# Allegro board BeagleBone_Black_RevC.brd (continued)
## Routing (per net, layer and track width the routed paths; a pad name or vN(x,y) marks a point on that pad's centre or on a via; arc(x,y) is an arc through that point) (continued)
PMIC_POWR_EN: length 66.7
  TOP w0.121: v1(18.29,14.24) U2.9 ; v1(48.92,23.61) U5.C6
  LYR3 w0.133: v1(18.29,14.24) 18.34,14.24 19.56,13.02 19.56,9.65 20.19,9.02 27.3,9.02 29.44,6.88 39.09,6.88 39.37,6.6 55.88,6.6 57.02,7.75 v1(57.02,10.92)
  LYR4 w0.133: v1(57.02,10.92) 56.39,10.92 54.48,12.83 54.48,14.86 52.58,16.76 51.31,16.76 50.67,17.4 50.67,20.7 48.92,22.45 v1(48.92,23.61)
PROC_A15: length 15.2
  TOP w0.121: v1(39.88,11.94) 38.86,12.95 38.86,15.88 38.34,16.4 38.34,20.18 39.62,21.46 40.37,21.46 40.92,22.01 U5.A15
  BOTTOM w0.121: v1(39.88,11.94) 40.39,12.45 41.4,12.45 R18.1
PWR_BUT: length 58
  TOP w0.121: v1(14.35,40.39) 11.56,40.39 10.83,41.11 S3.2 S3.4 ; U2.25 25.93,12.55 26.42,12.06 v1(26.92,12.06)
  LYR4 w0.133: v1(14.35,40.39) 14.35,40 15.89,38.46 15.89,24.03 17.44,22.48 19.05,22.48 21.21,20.32 24.13,20.32 25.65,18.8 25.65,13.34 v1(26.92,12.06) 28.57,10.41 28.57,3.17 P9.9
PWR_LEDR: length 2.3
  TOP w0.121: v1(3.05,17.27) 2.98,17.21 D1.1
  BOTTOM w0.121: R12.2 3.3,17.02 v1(3.05,17.27)
RBIAS: length 2.7
  TOP w0.121: v1(21.27,28.26) 21.91,28.89 21.91,29.21 22.06,29.36 U14.32
  BOTTOM w0.121: v1(21.27,28.26) R144.1
RCLKIN: length 7.8
  TOP w0.121: U14.5 25.33,27.94 25.34,27.94 v1(25.34,27.69)
  BOTTOM w0.121: 26.04,26.29 25.78,26.54 25.78,27.24 v1(25.34,27.69) ; 26.04,26.29 26.1,26.29 26.73,26.92 28.57,26.92 28.83,26.67 28.83,26.04 29.08,25.78 29.72,25.78 R140.2 ; 26.04,26.29 R142.2
REFCLKO: length 6.2
  TOP w0.121: U14.7 26.33,28.21 26.92,27.62 28.13,27.62 28.77,26.99 v1(29.21,26.99) R124.2 R118.1
  BOTTOM w0.121: R124.2 v1(29.21,26.99)
RXD0/MODE0: length 4.1
  TOP w0.121: U14.11 28.59,30.36 29.02,30.8 v1(29.21,30.8) 29.21,30.48 29.34,30.35 29.84,30.35 29.97,30.48 R128.2
  BOTTOM w0.121: R128.2 v1(29.21,30.8)
RXD1/MODE1: length 4
  TOP w0.121: R127.2 29.97,29.46 29.88,29.37 29.34,29.37 29.21,29.5 v1(29.21,29.84) 29.19,29.86 28.89,29.86 U14.10
  BOTTOM w0.121: R127.2 v1(29.21,29.84)
RXD2/RMIISEL: length 4.1
  TOP w0.121: U14.9 28.74,29.36 v1(29.21,28.89) 29.21,28.57 29.34,28.45 29.84,28.45 29.97,28.57 R126.2
  BOTTOM w0.121: R126.2 v1(29.21,28.89)
RXD3/PHYAD2: length 4.3
  TOP w0.121: R125.2 v1(29.21,27.94) 28.81,28.34 26.96,28.34 26.83,28.47 U14.8
  BOTTOM w0.121: R125.2 v1(29.21,27.94)
RXDV: length 2.8
  TOP w0.121: U14.26 22.28,32.37 21.72,32.92 21.72,33.27 21.34,33.66 v1(21.16,33.66)
  BOTTOM w0.121: R129.2 v1(21.16,33.66)
RXER/PHYAD0: length 4.1
  TOP w0.121: U14.13 28.83,31.37 v1(29.21,31.75) 29.21,31.4 29.34,31.27 29.88,31.27 29.97,31.37 R133.2
  BOTTOM w0.121: R133.2 v1(29.21,31.75)
RXN: length 18.4
  TOP w0.095: P5.2 17.14,33.92 16.89,34.17 16.26,34.17 16,33.92 16,32.64 16.64,32 17.64,32 18.43,32.79 19.29,32.79 20.09,31.99 20.09,30.39 20.66,29.83 20.94,29.83 v1(21.27,30.16) 21.34,30.23 21.9,30.23 22.03,30.36 U14.30
  BOTTOM w0.095: R121.1 v1(21.27,30.16)
  BOTTOM w0.121: C138.1 P5.2
RXP: length 15.9
  TOP w0.095: U14.31 22.02,29.86 21.93,29.95 21.68,29.95 21.53,29.79 21.53,29.46 v1(21.27,29.21) 20.94,29.55 20.54,29.55 19.81,30.28 19.81,31.88 19.18,32.51 18.54,32.51 17.75,31.72 16.52,31.72 15.72,32.52 15.72,34.04 15.47,34.29 P5.1
  BOTTOM w0.095: R120.1 v1(21.27,29.21)
  BOTTOM w0.121: C137.1 P5.1
SD_CLK: length 73.1
  TOP w0.121: R152.2 71.63,35.81 v1(72.01,35.43) ; v1(31.75,20.32) 31.75,20.7 29.97,22.48 R16.2 C5.1
  LYR3 w0.133: v1(72.01,35.43) 71.63,35.81 68.58,35.81 67.69,34.92 67.69,33.27 69.22,31.75 69.22,17.84 66.22,14.85 53.85,14.85 52.96,15.75 48.13,15.75 46.35,17.53 40.89,17.53 40.64,17.78 39.62,17.78 38.86,17.02 33.78,17.02 31.74,19.06 31.74,20.31 v1(31.75,20.32)
  BOTTOM w0.121: v1(72.01,35.43) 71.78,35.66 P10.5
SD_CMD: length 11
  TOP w0.121: R151.2 72.01,42.67 72.13,42.55 72.14,42.55 v1(72.52,42.16)
  BOTTOM w0.121: R15.2 69.09,38.35 69.58,37.86 P10.3 72.28,37.86 73.03,38.61 73.03,41.66 v1(72.52,42.16)
SD_DAT0: length 10.4
  BOTTOM w0.121: R153.2 72.77,28.26 73.53,29.02 73.53,31.22 71.29,33.46 P10.7 70.11,33.46 69.28,34.29 68.07,34.29 R31.2
SD_DAT1: length 11.4
  BOTTOM w0.121: R32.2 68.07,33.91 68.96,33.91 69.3,33.57 69.3,33.13 69.52,32.92 69.52,32.5 69.66,32.36 P10.8 71.91,32.36 73.15,31.11 73.15,29.22 72.91,28.96 71.76,28.96 71.5,28.7 R154.2
SD_DAT2: length 7.1
  TOP w0.121: R150.2 70.1,42.93 70.6,42.43 70.6,42.43 v1(70.87,42.16)
  BOTTOM w0.121: R2.2 68.33,41.27 69.54,40.06 P10.1 70.7,40.06 70.87,40.23 v1(70.87,42.16)
SD_DAT3: length 10.4
  TOP w0.121: R155.2 71.06,42.86 v1(71.75,42.16)
  BOTTOM w0.121: R13.2 68.96,39.24 69.24,38.96 P10.2 71.29,38.96 71.64,38.61 72.39,38.61 72.64,38.86 72.64,41.27 v1(71.75,42.16)
SPI1_CS0: length 76.1
  TOP w0.121: U11.25 63.75,35.31 v1(64.26,34.8) ; v1(43.32,23.61) U5.C12
  LYR4 w0.133: v1(43.32,23.61) 43.32,22.72 44.32,21.72 44.32,19.94 44.07,19.68 44.07,15.49 44.58,14.99 46.48,14.99 51.56,9.91 51.56,5.59 P9.28 ; v1(64.26,34.8) 64.77,34.29 69.85,34.29 71.12,33.02 71.12,18.41 70.36,17.65 69.28,17.65 66.1,14.48 61.59,14.48 58.92,11.8 57.66,11.8 v1(57.02,12.45)
  BOTTOM w0.121: v1(57.02,12.45) 57.53,11.94 57.53,8.25 54.61,5.33 53.59,5.33 P9.28
SPI1_D0: length 81.5
  TOP w0.121: v1(63.63,34.8) 63.25,35.17 U11.24 ; U5.B13 v1(42.52,22.81)
  LYR4 w0.133: v1(57.78,12.45) 58.19,12.04 58.78,12.04 61.47,14.73 65.85,14.73 69.15,18.03 70.23,18.03 70.87,18.67 70.87,32.89 69.72,34.04 64.39,34.04 v1(63.63,34.8) ; v1(42.52,22.81) 42.11,22.4 42.11,21.64 43.56,20.19 43.56,14.99 44.04,14.5 46.02,14.5 49.02,11.5 49.02,4.06 49.78,3.3 51.82,3.3 52.07,3.05 54.1,3.05 55.24,1.91
  BOTTOM w0.121: 55.24,1.91 56.26,2.92 56.26,6.48 57.78,8 v1(57.78,12.45)
SPI1_D1: length 26.9
  TOP w0.121: v1(43.32,24.41) U5.D12
  LYR4 w0.121: 43.72,23.11 43.72,24.01 v1(43.32,24.41)
  LYR4 w0.133: 43.72,23.11 44.7,22.13 44.7,19.81 44.32,19.42 44.32,15.75 44.83,15.24 46.74,15.24 53.98,8 53.98,7.24 55.24,5.97 55.24,4.45
SPI1_SCLK: length 81.1
  TOP w0.121: U5.A13 v1(42.52,22.01) ; U11.23 62.75,35.04 v1(62.99,34.8)
  LYR4 w0.133: v1(62.99,34.8) 64.01,33.78 69.6,33.78 70.61,32.77 70.61,18.92 70.1,18.41 69.02,18.41 65.6,14.99 61.09,14.99 v1(58.55,12.45) ; v1(42.52,22.01) 43.27,22.01 44.07,21.21 44.07,20.19 43.81,19.94 43.81,15.24 44.32,14.74 46.22,14.74 51.31,9.65 51.31,4.32 52.32,3.3 56.39,3.3 P9.31
  BOTTOM w0.121: P9.31 56.52,3.17 56.52,6.22 58.04,7.75 58.04,11.94 v1(58.55,12.45)
SYS_5V: length 117.7
  TOP w0.203: U2.2 19.15,17.04 v1(18.8,17.4) ; U2.42 23.06,19 v1(22.99,19.11) ; U2.21 23.86,11.45 v1(24.13,11.18) 24.26,11.31 U2.22 ; U2.39 v1(24.26,19.11) ; v1(26.92,16.45) 26.92,16.19 26.57,15.84 U2.32 ; U2.7 19.04,15.04 v1(18.8,14.8) 18.95,14.64 U2.8
  TOP w0.381: v1(7.62,45.33) 7.54,45.4 R74.1 ; R71.1 v1(7.62,44.45) ; R72.1 v1(7.62,47.31) ; R73.1 7.59,46.35 v1(7.62,46.39)
  TOP w0.762: RT1.1 67.88,8.19 C34.1
  LYR3 w0.381: 19.09,14.87 18.87,14.87 v1(18.8,14.8) 18.28,14.8 v1(18.24,14.84)
  LYR3 w0.508: 19.62,17.4 19.62,15.41 19.09,14.87 ; v1(8.81,15.24) 8.84,15.27 8.95,15.27 9.53,15.84 v1(9.53,15.86) 10.55,16.89 17.96,16.89 18.36,17.3 18.69,17.3 v1(18.8,17.4)
  LYR3 w0.762: 24.26,17.4 v1(24.26,19.11) ; 24.26,17.4 v1(18.8,17.4) ; 24.26,17.4 25.97,17.4 v1(26.92,16.45) 26.92,15.56 24.13,12.76 v1(24.13,11.18)
  LYR4 w0.381: v1(7.62,47.31) v1(7.62,46.39) v1(7.62,45.33) v1(7.62,44.45) 12.95,39.12 12.95,36.45 12.45,35.94 12.45,23.62 12.95,23.11 12.95,19.3 9.9,16.25 9.9,16.23 v1(9.53,15.86) ; 19.06,14.94 18.94,14.94 v1(18.8,14.8) 18.28,14.8 v1(18.24,14.84)
  LYR4 w0.508: 19.06,14.94 19.43,15.3 19.43,16.76 v1(18.8,17.4)
  LYR4 w0.762: P9.8 27.3,5.97 23.75,9.53 23.75,10.79 v1(24.13,11.18)
  LYR5_PWR w0.889: 28.04,3.71 P9.8 26.57,3.71 ; 67.17,9.03 RT1.1 ; RT1.1 67.17,7.48 ; RT1.1 68.72,7.48 ; RT1.1 68.72,9.03 ; 26.57,2.64 P9.7 28.04,2.64
  BOTTOM w0.381: U8.2 75.86,14.28 v1(75.54,14.61) 75.86,14.93 U8.3 ; v1(24.26,19.11) 24.26,18.48 C13.2 23.5,18.35 23.5,18.86 23.24,19.11 v1(22.99,19.11) ; C10.2 19.11,14.22 18.8,14.54 v1(18.8,14.8) ; v1(24.13,11.18) 23.81,11.49 C7.2 C8.2
  BOTTOM w0.508: 8.76,15.24 v1(8.81,15.24)
  BOTTOM w0.635: U4.2 9.54,15.88 v1(9.53,15.86)
  BOTTOM w0.762: P9.7 P9.8
SYS_RESETN: length 97.2
  TOP w0.121: v1(42.42,16.51) 41.91,16.51 41.66,16.76 41.66,18.8 42.8,19.94 43.81,19.94 44.7,20.83 44.7,21.46 45.32,22.08 U5.A10 ; S1.4 S1.2 v1(9.99,49.4) ; U16.4 31.1,5.7 P9.10
  LYR3 w0.133: v1(34.29,16.19) 34.73,15.75 38.1,15.75 38.35,16 41.91,16 v1(42.42,16.51)
  LYR4 w0.133: P9.10 28.96,5.33 28.96,10.73 v1(27.62,12.06) 27.62,12.89 30.48,15.75 30.48,18.29 v1(29.97,18.8) 28.83,19.94 28.83,22.99 29.72,23.88 29.72,36.34 v1(28.95,37.11) 27.77,38.28 22.16,38.28 11.04,49.4 v1(9.99,49.4)
  BOTTOM w0.121: v1(27.62,12.06) R14.2 C24.1 C30.1 ; v1(29.97,18.8) 30.48,18.29 30.48,16.51 30.8,16.19 P2.15 v1(34.29,16.19) ; U1.2 29.29,38.1 28.95,37.76 v1(28.95,37.11)
TCT_RCT: length 6.4
  BOTTOM w0.121: P5.4 15.88,29.21 P5.5 R137.1 C141.1
TESTOUT: length 2.9
  TOP w0.121: TP3.1 51.44,21.89 U5.A3
TIMER4: length 32.4
  TOP w0.121: v1(48.12,34.01) U5.R7
  LYR3 w0.121: 47.72,35.05 47.72,34.41 v1(48.12,34.01)
  LYR3 w0.133: v1(36.07,47.75) 36.34,47.48 40.02,47.48 41.4,46.1 41.4,44.45 46.75,39.1 46.75,36.31 47.72,35.34 47.72,35.05
  LYR4 w0.133: P8.7 27.3,49.02 28.57,47.75 33.4,47.75 34.04,48.39 35.43,48.39 v1(36.07,47.75)
TIMER5: length 28.8
  TOP w0.121: v1(48.92,34.81) U5.T6
  LYR3 w0.133: v1(48.92,34.81) 48.92,35.15 48.39,35.69 48.39,38.61 42.14,44.86 42.14,46.38 40.13,48.39 v1(36.83,48.39)
  LYR4 w0.133: P8.9 30.86,49.15 36.07,49.15 v1(36.83,48.39)
TIMER6: length 35.7
  TOP w0.121: U5.U6 48.92,35.61 48.92,37.24 49.4,37.72 49.4,38.35 49.02,38.73 49.02,43.84 v1(49.25,44.07)
  BOTTOM w0.121: v1(49.25,44.07) 49.25,44.04 49.15,43.94 47.5,43.94 46.99,44.45 40.01,44.45 38.86,45.59 38.86,50.93 38.23,51.56 30.99,51.56 P8.10
TIMER7: length 32.7
  TOP w0.121: v1(48.12,34.81) U5.T7
  LYR3 w0.133: v1(36.07,48.39) 36.58,47.88 40.13,47.88 41.78,46.23 41.78,44.58 48.12,38.24 v1(48.12,34.81)
  LYR4 w0.133: P8.8 28.57,51.44 28.57,49.78 29.59,48.77 35.69,48.77 v1(36.07,48.39)
TXCLK: length 6
  TOP w0.121: v1(29.21,35.56) 28.83,35.18 27.94,35.18 27.67,35.45 26.55,35.45 25.33,34.24 U14.20
  BOTTOM w0.121: R134.2 v1(29.21,35.56)
TXD0: length 4.2
  TOP w0.121: R39.2 21.84,35.94 23.11,34.67 23.65,34.67 24.33,33.99 U14.22
TXD1: length 3.3
  TOP w0.121: R40.2 22.1,35.05 22.73,34.42 23.33,34.42 23.83,33.92 U14.23
TXD2: length 7.8
  TOP w0.121: U14.24 23.33,33.92 23.11,34.14 22.5,34.14 22.07,34.58 19.4,34.58 19.18,34.8 19.18,36.45 19.56,36.83 R41.2
TXD3: length 8.6
  TOP w0.121: R42.2 19.82,37.72 18.8,36.7 18.8,34.67 19.3,34.16 21.21,34.16 21.32,34.05 21.32,34.05 21.56,33.82 21.56,33.81 22.05,33.32 22.05,33.09 22.28,32.87 U14.25
TXEN: length 1.7
  TOP w0.121: R38.2 25.02,34.92 25.02,34.42 24.83,34.24 U14.21
TXN: length 20.3
  TOP w0.095: v1(21.27,32.07) 21.27,31.69 21.59,31.37 U14.28
  LYR3 w0.102: v1(21.27,32.07) 20.88,31.68 20.88,31.16 19.81,30.09 19.81,28.45 18.21,26.85 16.71,26.85 15.9,27.66 15.9,29.09 16.15,29.34 16.89,29.34 17.14,29.09 P5.6
  BOTTOM w0.095: R123.1 v1(21.27,32.07)
  BOTTOM w0.121: P5.6 C140.1
TXP: length 17.8
  TOP w0.095: v1(21.27,31.11) 21.27,31.1 21.28,31.09 21.81,31.09 22.03,30.86 U14.29
  LYR3 w0.102: P5.3 15.6,30.76 15.6,27.53 16.59,26.54 18.34,26.54 20.12,28.32 20.12,29.96 v1(21.27,31.11)
  BOTTOM w0.095: R122.1 v1(21.27,31.11)
  BOTTOM w0.121: C139.1 P5.3
U5_H18: length 4.2
  TOP w0.121: U5.H18 38.1,28.01 37.9,27.81 R28.1
U5_R13: length 10.5
  TOP w0.121: v1(42.52,34.01) U5.R13
  LYR3 w0.121: v1(42.52,34.01) 42.92,34.41 42.92,35.06 42.55,35.43
  LYR3 w0.133: 42.55,35.43 41.91,36.07 41.02,36.07 38.42,38.67 v1(38.42,40.64)
  BOTTOM w0.121: v1(38.42,40.64) R160.1
U5_T13: length 9.9
  TOP w0.121: v1(42.52,34.81) U5.T13
  LYR3 w0.133: v1(37.15,40.64) 37.15,39.31 40.89,35.56 41.78,35.56 42.26,35.09 42.26,35.07 v1(42.52,34.81)
  BOTTOM w0.121: v1(37.15,40.64) R161.1
UART0_RX: length 35.3
  TOP w0.121: v1(40.92,25.21) U5.E15
  LYR4 w0.121: 39.75,25.53 39.83,25.61 40.52,25.61 v1(40.92,25.21)
  LYR4 w0.133: 39.75,25.53 39.19,24.97 39.19,20.24 40.41,19.02 40.41,10.69 v1(39.88,10.16)
  BOTTOM w0.121: U15.6 53.22,11.68 52.32,12.57 50.16,12.57 49.53,11.94 49.53,10.41 48.51,9.4 44.45,9.4 44.2,9.65 40.39,9.65 39.88,10.16 v1(39.88,10.16)
UART0_TX: length 32.2
  TOP w0.121: v1(40.12,25.21) U5.E16
  LYR4 w0.133: v1(40.12,25.21) 39.45,24.54 39.45,21.38 40.65,20.19 40.65,10.66 v1(41.15,10.16)
  BOTTOM w0.121: U15.5 53.23,12.18 52.58,12.83 49.91,12.83 49.28,12.19 49.28,10.67 48.26,9.65 44.7,9.65 44.45,9.91 41.4,9.91 v1(41.15,10.16)
UART1_RXD: length 25.6
  TOP w0.121: v1(40.12,24.41) U5.D16
  LYR4 w0.121: 40.52,21.72 40.52,24.01 v1(40.12,24.41)
  LYR4 w0.133: v1(45.09,8.89) 44.45,9.53 44.45,10.79 41.66,13.59 41.66,20.45 40.52,21.58 40.52,21.72
  BOTTOM w0.121: P9.26 48.77,5.84 47.75,5.84 46.35,7.24 46.35,8.13 45.59,8.89 v1(45.09,8.89)
UART1_TXD: length 23.5
  TOP w0.121: v1(40.92,24.41) U5.D15
  LYR4 w0.121: v1(40.92,24.41) 41.32,24.01 41.32,23.37
  LYR4 w0.133: 41.32,23.37 41.33,23.35 41.33,21.28 41.91,20.7 41.91,13.84 44.07,11.68 44.45,11.68 46.35,9.78 46.35,5.71 P9.24
UART2_RXD: length 22.7
  TOP w0.121: P9.22 43.56,5.97 41.66,5.97 38.61,9.02 38.61,15.75 38.09,16.26 38.09,20.31 39.72,21.94 39.72,22.17 39.72,22.18 U5.A17
UART2_TXD: length 26
  TOP w0.121: P9.21 43.81,3.17 43.81,4.83 43.05,5.59 41.53,5.59 38.35,8.76 38.35,15.62 37.85,16.13 37.85,20.45 39.32,21.92 39.32,22.81 U5.B17
UART4_RXD: length 40.9
  TOP w0.121: v1(36.07,36) 36.64,35.43 36.96,35.43 37.58,34.81 39.32,34.81 U5.T17
  LYR4 w0.133: v1(36.07,36) 35.94,36.13 35.37,36.13 34.54,35.31 34.54,22.99 34.29,22.73 34.29,17.53 33.15,16.38 v1(33.15,6.48)
  BOTTOM w0.121: P9.11 33.66,3.17 33.66,5.4 33.15,5.91 v1(33.15,6.48)
UART4_TXD: length 44.5
  TOP w0.121: U5.U17 39.48,35.21 39.08,35.61 37.67,35.61 37.34,35.94 37.34,37.08 v1(36.83,37.59) ; P9.13 33.66,3.17 33.66,5.08 v1(32.26,6.48)
  LYR4 w0.133: v1(36.83,37.59) 36.42,38 35.71,38 34.04,36.32 34.04,23.24 33.78,22.99 33.78,18.03 32.26,16.51 v1(32.26,6.48)
USB0_DM: length 40.1
  TOP w0.114: U5.N18 38.8,32.13 36.82,32.13 36.07,32.88 36.07,34.26 35.69,34.65 35.2,34.65 33.43,36.42 28.46,36.42 28.08,36.8 23.89,36.8 17.89,42.8 13.13,42.8 13.02,42.69 13.02,42.01 12.92,41.91 U10.2 v1(11.94,41.91)
  BOTTOM w0.114: P4.2 7.04,43.33 7.24,43.54 7.9,43.54 8.79,42.65 11.44,42.65 11.54,42.55 11.54,41.88 11.64,41.78 11.84,41.78 11.94,41.88 v1(11.94,41.91)
USB0_DP: length 40.2
  TOP w0.114: U5.N17 39.32,32.41 36.94,32.41 36.35,32.99 36.35,34.41 35.83,34.92 35.32,34.92 33.54,36.7 28.57,36.7 28.19,37.08 24,37.08 18.01,43.08 12.98,43.08 12.57,42.67 12.57,42.42 U10.1 12.07,42.41 v1(11.94,42.55)
  BOTTOM w0.114: P4.3 6.92,44.13 7.24,43.81 8.02,43.81 8.9,42.93 11.56,42.93 11.82,42.66 11.82,42.66 v1(11.94,42.55)
USB0_ID: length 47.5
  TOP w0.121: v1(15.11,41.4) 14.61,40.89 12.71,40.89 12.58,41.02 U10.3 ; U5.P16 v1(40.12,33.21)
  BOTTOM w0.121: v1(40.12,33.21) 40.52,33.61 40.52,35.05 40.45,35.12 40.45,39.18 40.15,39.48 32.89,39.48 32.56,39.81 28.63,39.81 28.43,40.01 24.38,40.01 23.86,39.48 17.04,39.48 v1(15.11,41.4) 15.11,42.16 13.21,44.07 8.76,44.07 7.98,44.85 7.11,44.85 7.03,44.93 P4.4
USB1_DM: length 69.3
  TOP w0.114: U5.R18 38.8,33.73 38.43,33.73 38.1,33.4 v1(38.1,33.15)
  LYR3 w0.127: v1(78.08,17.14) 77.9,17.32 76.68,17.32 76.06,16.7 74.21,16.7 P3.2 70.11,15.83 68.07,13.79 47.5,13.79 46.61,14.68 40.77,14.68 39.29,13.21 v1(36.07,13.21)
  LYR4 w0.127: v1(38.1,33.15) 37.72,32.77 37.72,22.81 37.26,22.35 37.26,20.65 37.72,20.19 37.72,15.06 36.47,13.81 36.47,13.61 v1(36.07,13.21)
  BOTTOM w0.114: U9.2 78.55,18.41 78.33,18.19 77.93,18.19 77.68,17.94 77.68,17.54 v1(78.08,17.14)
USB1_DP: length 69.3
  TOP w0.114: U5.R17 39.32,34.01 38.32,34.01 v1(37.47,33.15)
  LYR3 w0.127: v1(78.08,17.78) 77.92,17.63 76.56,17.63 75.93,17.01 74.17,17.01 P3.3 73.34,17.72 71.77,16.14 69.99,16.14 67.94,14.1 47.62,14.1 46.74,14.99 40.64,14.99 39.17,13.51 36.4,13.51 v1(36.07,13.84)
  LYR4 w0.127: v1(36.07,13.84) 37.41,15.19 37.41,20.07 36.96,20.52 36.96,22.48 37.41,22.94 37.41,33.1 v1(37.47,33.15)
  BOTTOM w0.114: v1(78.08,17.78) 78.21,17.92 U9.1
USB1_DRVVBUS: length 52.5
  TOP w0.121: U5.F15 v1(40.92,26.01)
  LYR3 w0.133: v1(42.42,14.1) 43.05,13.46 68.58,13.46 69.85,14.73 74.3,14.73 75.14,15.58 v1(75.56,15.58)
  LYR4 w0.121: v1(40.92,26.01) 41.32,25.61 41.32,25.04 41.55,24.81 42.12,24.81 v1(42.52,24.41)
  BOTTOM w0.121: R53.1 76.81,17.14 77.04,16.92 U8.4 v1(75.56,15.58) ; v1(42.42,14.1) 41.91,14.61 41.91,17.27 42.99,18.35 42.99,23.11 42.92,23.18 42.92,24.01 v1(42.52,24.41)
USB1_ID: length 1.9
  TOP w0.121: U5.P17 39.37,33.16 v1(39.32,33.21)
  BOTTOM w0.121: v1(39.32,33.21) 39.32,33.71 39.05,33.97 R49.2
USB1_OCN: length 72.7
  TOP w0.121: v1(40.12,34.81) U5.T16
  LYR3 w0.133: v1(39.88,13.21) 68.83,13.21 70.1,14.48 74.42,14.48 75.06,15.11 77.6,15.11 78.49,16 82.01,16 v1(83.16,17.14)
  LYR4 w0.133: v1(40.12,34.81) 39.76,34.81 38.73,33.78 38.73,32.89 38.1,32.26 38.1,22.61 37.84,22.35 37.84,21.51 38.1,21.25 38.1,14.99 v1(39.88,13.21)
  BOTTOM w0.121: U8.5 82.86,15.58 83.16,15.88 v1(83.16,17.14) R52.2
USB1_PWR: length 32.7
  TOP w0.635: v1(83.15,14.93) 83.15,15.88 v1(81.89,17.14)
  BOTTOM w0.305: U9.6 81.88,17.92 C35.1
  BOTTOM w0.381: C35.1 v1(81.89,17.14) ; 83.15,13.63 U8.8 ; 83.15,14.28 U8.7 ; FB7.1 R37.2 ; U8.6 v1(83.15,14.93)
  BOTTOM w0.508: v1(83.15,14.93) 83.15,12.95 82.4,12.19 74.42,12.19 72.01,9.78 67.31,9.78 67,10.09 FB7.1
USB1_VBUS: length 66.8
  TOP w0.305: U5.T18 37.23,34.41 36.84,34.8 v1(36.83,34.8)
  LYR3 w0.203: v1(29.97,19.56) 30.73,19.56 32.89,17.4 32.89,15.37 35.69,12.57 43.69,12.57 44.2,12.06 55.5,12.06 56.32,12.89 61.79,12.89 v1(62.23,12.45) ; v1(31.75,37.15) 31.75,36.83 32,36.58 33.53,36.58 35.31,34.8 v1(36.83,34.8)
  LYR4 w0.203: v1(31.75,37.15) 30.23,35.62 30.23,23.62 29.97,23.37 v1(29.97,19.56)
  BOTTOM w0.203: v1(62.23,12.45) 62.23,11.43 62.48,11.18 R37.1
USB_DC: length 61.6
  TOP w0.121: U10.6 14.09,42.41 v1(14.1,42.4)
  TOP w0.203: U2.12 19.79,12.85 19.79,12.85
  TOP w0.508: 19.41,12.28 19.79,12.66 19.79,12.85 ; v1(12.7,16.26) C1.2
  LYR4 w0.508: v1(18.85,11.68) 18.83,11.7 v1(18.83,12.28) 16.13,14.99 13.97,14.99 v1(12.7,16.26) 12.7,17.02 14.56,18.88 14.56,19.96 13.75,20.76 13.75,23.42 13.16,24.02 13.16,35.56 13.77,36.17 13.77,39.2 13.82,39.26 v1(13.82,39.83) 13.31,40.34 13.31,41.61 v1(14.1,42.4)
  BOTTOM w0.121: v1(14.1,42.4) 14.61,41.89 14.61,41.02 17.21,38.42 R159.1
  BOTTOM w0.381: C36.1 13.25,41.44 13.7,41.9 13.7,42.01 v1(14.1,42.4)
  BOTTOM w0.508: v1(13.82,39.83) 13.04,40.6 C36.1 12.36,41.44 12.19,41.27 7.8,41.27 6.55,42.53 P4.1
USR0: length 34.9
  TOP w0.121: v1(13.02,44.77) Q1.2 ; v1(14.8,44.77) 17.97,44.77 24.64,38.1 33.91,38.1 35.31,39.5 37.59,39.5 39.5,37.59 40.13,37.59 41.32,36.4 U5.V15
  BOTTOM w0.121: R76.1 v1(13.02,44.77) v1(14.8,44.77)
USR1: length 38.6
  TOP w0.121: U5.U15 40.92,35.61 40.92,36.42 40.01,37.34 39.37,37.34 37.47,39.24 35.56,39.24 34.16,37.85 24.38,37.85 18.1,44.13 14.67,44.13 14.29,44.51 v1(14.29,47.31) 14.29,47.75 14.1,47.94 13.21,47.94 13.02,47.75 Q1.5
  BOTTOM w0.121: R77.1 v1(14.29,47.31)
USR2: length 38.9
  TOP w0.121: v1(9.53,44.77) Q2.2 ; v1(40.92,34.81) U5.T15
  LYR3 w0.133: v1(9.53,44.77) 9.53,43.43 13.84,39.12 23.75,39.12 24.26,39.62 36.11,39.62 v1(40.92,34.81)
  BOTTOM w0.121: v1(9.53,44.77) R78.1
USR3: length 40.3
  TOP w0.121: U5.V16 40.52,36.44 39.87,37.09 39.24,37.09 37.34,38.99 35.81,38.99 34.42,37.59 24.26,37.59 18.16,43.69 14.48,43.69 14.22,43.94 11.94,43.94 11.3,44.58 11.3,46.8 v1(10.79,47.31) 10.79,47.69 10.54,47.94 9.78,47.94 9.53,47.69 Q2.5
  BOTTOM w0.121: R79.1 v1(10.79,47.31)
VDCDC1: length 5.5
  BOTTOM w0.381: v1(20.07,9.91) 20.07,8.89 L1.2 20.7,8.89 v1(20.7,9.91) v1(20.07,9.91) ; v1(20.07,9.91) 19.04,9.91 18.8,9.66 R6.1
VIO: length 27.8
  TOP w0.121: U16.5 32.4,8.12 32.14,8.38 v1(30.23,8.38) ; R7.2 10.92,15.37 11.81,14.48 v1(12.7,14.48) ; U2.18 22.66,11.67 22.16,11.18 v1(22.1,11.18)
  LYR3 w0.133: v1(22.1,11.18) 22.99,11.18 23.75,10.41 28.19,10.41 v1(30.23,8.38)
  LYR4 w0.133: v1(22.1,11.18) 21.58,10.66 18.8,10.66 18.12,11.33 18.12,12.1 15.75,14.48 v1(12.7,14.48)
VLDO1: length 10.6
  TOP w0.203: U2.3 18.42,16.64
  TOP w0.381: R8.1 R7.1 11.94,15.37 12.19,15.11 16.38,15.11 16.7,15.43 R5.1 17.65,15.88 18.42,16.64
VREFP_ADC: length 7.7
  TOP w0.121: 45.59,21.72 45.72,21.84 45.72,22.81
  TOP w0.254: 45.72,22.81 U5.B9
  TOP w0.305: 45.29,21.42 45.59,21.72
  TOP w0.381: 45.29,21.42 45.21,21.34 45.21,20.65 44.1,19.54 R27.2 44.1,18.32 C33.1 C31.1 C32.1
VRTC: length 43.6
  TOP w0.254: v1(48.12,24.41) U5.D7
  TOP w0.381: v1(18.03,17.91) 17.59,17.46 C16.1 16.7,16.89 16.45,16.64 15.94,16.64 15.68,16.38 R5.2
  LYR3 w0.381: v1(18.8,21.08) 19.16,20.72 25.55,20.72 27.3,22.48 32,22.48 32.77,23.24 34.54,23.24 35.31,22.48 35.31,21.21 35.69,20.83 38.61,20.83 39.77,19.66 40.75,19.66 41.02,19.94 46.35,19.94 47.31,20.89 v1(47.31,20.95)
  LYR4 w0.381: v1(18.8,21.08) 18.03,20.32 v1(18.03,17.91)
  BOTTOM w0.178: R26.1 49.82,19.18 49.69,19.3 49.69,20.67 49.4,20.95 v1(49.21,20.95)
  BOTTOM w0.381: C105.1 v1(47.31,20.95)
WAKEUP: length 60.9
  TOP w0.121: U2.13 20.66,11.22 v1(20.7,11.18) ; U5.C5 v1(49.72,23.61)
  LYR3 w0.133: v1(57.02,11.68) 56.52,11.18 56.52,10.03 55.88,9.4 42.16,9.4 40.64,7.87 28.96,7.87 27.43,9.4 24.13,9.4 22.86,10.67 21.21,10.67 v1(20.7,11.18)
  LYR4 w0.133: v1(49.72,23.61) 49.28,23.16 49.28,22.55 51.56,20.26 51.56,17.53 51.94,17.14 52.7,17.14 54.86,14.99 54.86,13.84 v1(57.02,11.68)
  BOTTOM w0.121: R26.2 50.16,22.5 50.12,22.54 50.12,23.21 v1(49.72,23.61)
WP: length 28.1
  BOTTOM w0.121: U7.5 28.23,23.26 27.98,23.51 25.81,23.51 25.55,23.26 25.55,22.54 25.43,22.42 R156.2 24.64,22.42 23.54,23.51 21.23,23.51 20.07,22.35 15.11,22.35 11.81,19.05 TP4.1
XDMA_EVENT_INTR0: length 16.4
  BOTTOM w0.121: P2.17 34.23,17.46 34.92,16.76 34.92,15.37 36,14.29 40.48,14.29 42.38,12.39 42.38,11.02 42.28,10.92 R18.2 41.91,10.79 42.25,10.45 U6.1
YEL_C: length 3.2
  TOP w0.121: v1(4.32,27.94) 4.32,27.03 P5.11
  BOTTOM w0.121: R130.2 v1(4.32,27.94)
YELA: length 27.8
  TOP w0.121: v1(23.69,27.69) 23.83,27.83 U14.2
  LYR3 w0.133: P5.12 4.88,24.31 7.11,26.54 12.06,26.54 14.61,24 17.78,24 21.08,27.3 21.72,27.3 22.61,28.19 23.18,28.19 v1(23.69,27.69)
  BOTTOM w0.121: P5.12 4.88,24.77 5.21,25.1 R135.1
ZQ: length 2.5
  TOP w0.121: v1(66.3,22.36) U12.L8
  BOTTOM w0.121: v1(66.3,22.36) 66.7,21.96 R99.2
N21667305: length 2.1
  TOP w0.121: v1(67.44,45.21) 67.25,45.03 U11.49
  BOTTOM w0.121: v1(67.44,45.21) 67.44,45.09 R149.1
N21757673: length 4.1
  TOP w0.121: R10.1 C19.1 v1(9.53,18.41)
  BOTTOM w0.121: U4.4 v1(9.53,18.41) C19.1
N21769115: length 6.7
  TOP w0.121: S2.1 S2.3 73.66,44.13 R75.2
N22155575: length 24.4
  TOP w0.121: v1(40.92,33.21) U5.P15
  LYR5_PWR w0.121: v1(40.92,33.21) 41.32,33.61 41.32,37.43 41.07,37.68 40.72,37.68 40.48,37.93 40.48,38.52 v1(40.01,38.99)
  BOTTOM w0.121: R159.2 24,39.12 24.51,39.62 28.32,39.62 28.45,39.5 32.38,39.5 32.89,38.99 v1(40.01,38.99)
N22248684: length 1.7
  TOP w0.121: v1(40.96,43.18) 41.15,42.99 Y4.3
  BOTTOM w0.121: R167.1 v1(40.96,43.18)
N22248838: length 1.9
  BOTTOM w0.121: U6.5 48.13,12.41 48.26,12.28 R21.1
N22287501: length 12.5
  TOP w0.121: U3.4 40.97,47.07 40.29,47.75 39.24,47.75 38.1,48.9 31.11,48.9 v1(30.48,48.26)
  BOTTOM w0.121: v1(30.48,48.26) R162.1
N22287555: length 15.1
  TOP w0.121: U3.2 40.32,44.06 40.44,43.94 42.04,43.94 42.42,43.56 42.42,39.5 41.78,38.86 41.27,38.86 v1(41.15,38.99) ; v1(41.72,34.01) U5.R14
  LYR5_PWR w0.121: v1(41.15,38.99) 41.37,38.77 41.7,38.77 41.95,38.53 41.95,38.05 41.7,37.81 41.66,37.81 41.66,35.56 42.12,35.1 42.12,34.41 v1(41.72,34.01)
N22420400: length 9.8
  TOP w0.203: U2.4 18.91,16.24 v1(18.8,16.13) 19.09,15.84 U2.5
  LYR3 w0.381: TP5.1 14.73,12.95 17.91,16.13 v1(18.8,16.13)
N22420444: length 10.5
  TOP w0.203: U2.6 v1(18.29,15.44)
  LYR3 w0.203: v1(18.29,15.44) 17.87,15.44 16,13.57 16,9.4 TP6.1
N22420447: length 4.1
  TOP w0.203: TP7.1 18.29,11.68 18.29,12.45 19.28,13.44 U2.11
N22488252: length 24.6
  TOP w0.121: U5.E17 39.32,25.21 38.17,25.21 37.72,24.77 35.81,24.77 34.16,23.11 34.16,19.3 33.53,18.67 32.38,18.67 30.99,20.07 30.99,20.83 28.19,23.62 25.02,23.62 TP9.1

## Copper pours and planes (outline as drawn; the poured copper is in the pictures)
DGND on TOP (solid shape): 81.25,12.7 77.44,12.7 77.44,16.51 81.25,16.51
DGND on TOP: 38.73,43.43 38.99,43.69 41.66,43.69 41.91,43.43 41.91,39.62 41.66,39.37 38.99,39.37 38.73,39.62
DGND on BOTTOM: 41.27,30.48 41.4,30.61 41.4,30.99 41.91,30.99 41.91,30.61 42.16,30.35 42.16,29.72 41.91,29.46 41.91,29.08 41.27,29.08
DGND on BOTTOM: 19.56,16.07 19.56,15.3 19.81,15.05 20.7,15.05 20.95,14.8 20.95,13.14 20.7,12.89 19.94,12.89 19.68,12.64 19.68,12.26 19.94,12 22.61,12 22.86,12.26 22.86,13.53 23.11,13.78 24.13,13.78 24.38,14.03 24.38,14.67 25.15,14.67 25.15,14.41 25.4,14.16 26.04,14.16 26.29,14.41 26.29,16.07 26.04,16.32 25.4,16.32 25.15,16.07 25.15,15.81 24.38,15.81 24.38,16.07 24.13,16.32 23.5,16.32 23.24,16.07 23.24,15.81 22.48,15.81 22.48,16.07 22.23,16.32 21.59,16.32 21.34,16.07 21.34,15.81 20.57,15.81 20.57,16.07 20.32,16.32 19.81,16.32
DGND on BOTTOM: 69.6,22.86 69.85,22.61 72.26,22.61 72.52,22.86 72.52,23.5 72.39,23.62 71.25,23.62 71.12,23.75 71.12,26.29 70.99,26.42 69.85,26.42 69.6,26.16
DGND on BOTTOM: 6.16,45.53 7.75,45.53 8.7,44.58 8.94,44.58 9.09,44.73 9.09,46.09 9.32,46.32 9.69,46.32 9.77,46.39 9.77,49.03 9.37,49.43 7.86,49.43 6.69,48.26 6.69,46.96 5.94,46.22 5.94,45.75
DGND on LYR2_GND: outline of 81 points within 1.91,1.27 84.14,53.34
GND_EARTH on TOP: 6.35,0.64 2.31,2.31 0.64,6.35 0.64,48.26 2.31,52.3 6.35,53.98 73.66,53.98 82.19,50.44 85.72,41.91 85.72,12.7 82.19,4.17 73.66,0.64 ; 1 cut-out
GND_EARTH on BOTTOM: 6.35,0.64 2.31,2.31 0.64,6.35 0.64,48.26 2.31,52.3 6.35,53.98 73.66,53.98 82.19,50.44 85.72,41.91 85.72,12.7 82.19,4.17 73.66,0.64 ; 1 cut-out
GND_EARTH on LYR5_PWR: 6.35,0.64 2.31,2.31 0.64,6.35 0.64,48.26 2.31,52.3 6.35,53.98 73.66,53.98 82.19,50.44 85.72,41.91 85.72,12.7 82.19,4.17 73.66,0.64 ; 1 cut-out
GND_OSC0 on BOTTOM: 42.67,38.86 41.91,38.86 41.66,39.12 41.66,42.93 41.91,43.18 48.51,43.18 48.77,42.93 48.77,39.12 48.51,38.86 47.75,38.86 47.75,39.5 47.62,39.62 42.67,39.62
GND_OSC1 on TOP: 48.51,18.03 48.26,17.78 48.26,10.16 48.51,9.91 53.72,9.91 53.98,10.16 53.98,17.78 53.72,18.03 ; 1 cut-out
VDD_1V8 on LYR3: 41.91,34.54 42.16,34.29 42.16,33.02 41.91,32.77 41.27,32.77 40.77,32.26 33.02,32.26 32.77,32.51 32.77,34.29 33.02,34.54
VDD_1V8 on LYR4: 45.72,25.15 45.47,24.89 41.66,24.89 41.4,25.15 41.4,28.45 41.15,28.7 40.01,28.7 39.75,28.96 39.75,34.29 40.01,34.54 42.55,34.54 42.8,34.8 42.8,36.32 43.05,36.58 54.86,36.58 55.12,36.32 55.12,35.31 54.86,35.05 45.97,35.05 45.72,34.8 45.72,29.72 45.34,29.34 45.34,29.08 45.72,28.7
VDD_1V8 on LYR5_PWR: 32.51,34.29 32.26,34.04 32.26,28.19 29.59,25.53 29.59,25.27 27.69,23.37 27.69,21.84 26.42,20.57 26.42,17.53 26.67,17.27 30.73,17.27 30.99,17.53 30.99,20.57 33.78,23.37 33.78,34.04 33.53,34.29
VDD_1V8 on LYR5_PWR: 44.7,13.97 44.7,25.27 44.83,25.4 46.74,25.4 46.86,25.27 46.86,20.45 47.24,20.07 48.9,20.07 49.15,19.81 49.15,13.97 48.9,13.72 44.96,13.72
VDD_3V3A on BOTTOM: 48.13,33.02 50.04,33.02 50.29,33.27 50.29,35.18 50.76,35.64 50.76,36.45 50.29,36.45 50.29,35.81 49.91,35.43 49.91,33.91 49.53,33.91 49.53,35.43 49.15,35.81 49.15,36.45 48.69,36.45 48.69,35.86 48.26,35.43 48.26,33.66 48.01,33.4 48.01,33.15
VDD_3V3A on BOTTOM: 39.88,29.72 40.39,29.72 40.77,29.34 40.77,29.08 41.02,28.83 41.66,28.83 41.91,28.57 41.91,27.56 41.4,27.56 41.4,27.94 41.02,28.32 40.51,28.32 40.26,28.57 38.61,28.57 38.61,29.08 39.24,29.08
VDD_3V3A on BOTTOM: 42.29,36.45 42.29,35.81 41.91,35.43 41.91,33.27 42.16,33.02 43.31,33.02 43.43,33.15 43.43,33.27 43.05,33.66 43.05,35.56 42.76,35.85 42.76,36.45
VDD_3V3A on LYR5_PWR: 21.59,11.68 21.34,11.94 21.34,23.37 21.59,23.62 27.18,23.62 27.43,23.37 27.43,22.1 26.16,20.83 26.16,17.4 26.54,17.02 30.86,17.02 31.24,17.4 31.24,20.45 34.04,23.24 34.04,34.04 33.27,34.8 32.51,34.8 32.26,35.05 32.26,37.08 37.85,42.67 37.85,45.97 38.1,46.23 41.27,46.23 41.53,45.97 41.53,44.96 41.78,44.7 49.53,44.7 52.2,47.37 73.15,47.37 73.41,47.12 73.41,45.34 73.15,45.09 68.96,45.09 68.07,45.97 59.94,45.97 59.05,45.09 54.23,45.09 53.85,44.7 53.85,34.8 53.59,34.54 50.55,34.54 50.16,34.16 50.16,31.5 49.15,30.48 49.15,29.46 48.9,29.21 42.55,29.21 42.04,28.7 42.04,28.32 41.91,28.19 40.64,28.19 40.39,27.94 40.39,27.3 40.64,27.05 41.91,27.05 42.16,26.8 42.16,26.54 41.15,25.53 41.15,24.89 41.4,24.64 42.8,24.64 43.05,24.89 43.05,25.27 43.18,25.4 44.32,25.4 44.45,25.27 44.45,13.84 44.83,13.46 48.9,13.46 49.15,13.21 49.15,5.59 48.9,5.33 39.88,5.33 39.62,5.59 39.62,11.3 39.24,11.68
VDD_3V3B on BOTTOM: 74.3,27.18 74.3,27.05 74.04,26.8 74.04,25.27 73.15,24.38 71.63,24.38 71.5,24.51 71.5,25.4 71.63,25.53 72.01,25.53 72.52,26.04 72.52,26.42 73.15,26.42 73.15,26.92 72.52,26.92 72.52,27.18 72.64,27.3 74.17,27.3
VDD_3V3B on BOTTOM: 25.08,35.24 24.13,35.24 24.13,36.2 24.38,36.45 26.04,36.45 26.54,35.94 26.54,34.29 26.35,34.1 26.35,33.53 25.75,33.53 25.08,34.2
VDD_3V3B on BOTTOM: 10.05,17.44 8.59,17.44 8.48,17.34 8.48,16.46 8.6,16.34 9.53,16.34 10.08,16.9 10.08,17.4
VDD_3V3B on LYR5_PWR: outline of 90 points within 1.91,1.27 84.14,53.34
VDD_5V on TOP: 19.26,13.94 10.92,13.94 10.41,13.43 10.41,9.65 10.92,9.14 12.45,9.14 12.95,9.65 12.95,11.68 13.46,12.19 17.56,12.19 18.99,13.62 19.25,13.62 19.37,13.74 19.37,13.89 19.32,13.94 19.27,13.94
VDD_CORE on TOP: 27.3,14.1 27.3,12.95 27.56,12.7 29.21,12.7 29.46,12.95 29.46,13.84 31.37,13.84 31.5,13.97 31.5,14.73 31.38,14.85 26.6,14.85 26.49,14.74 25.91,14.74 25.91,14.54 26.86,14.54
VDD_CORE on LYR3: 49.15,25.53 45.97,25.53 45.72,25.78 45.72,26.92 45.34,27.3 42.42,27.3 42.16,27.05 42.16,24.13 41.91,23.88 32.77,23.88 32,24.64 32,25.65 32.51,26.16 33.27,26.16 33.53,26.42 33.53,27.43 33.78,27.69 40.26,27.69 40.26,29.21 41.15,29.21 41.15,30.23 40.51,30.23 40.01,30.73 40.01,31.11 40.39,31.5 41.4,31.5 41.78,31.88 43.43,31.88 45.21,33.66 49.15,33.66 49.4,33.4 49.4,25.78
VDD_MPU on TOP: 25.21,11.75 25.02,11.75 25.02,12.38 25.72,12.38 26.54,11.56 27.94,11.56 27.94,11.18 27.3,10.54 27.3,8.64 27.05,8.38 26.29,8.38 25.91,8.76 25.91,11.05
VDD_MPU on LYR3: 45.47,21.08 45.47,26.8 45.21,27.05 42.55,27.05 42.42,26.92 42.42,23.62 41.27,22.48 35.94,22.48 35.81,22.35 35.81,21.34 35.94,21.21 40.13,21.21 40.51,20.83 45.21,20.83
VDD_PHYA on LYR5_PWR: 10.54,23.5 9.27,22.23 2.54,22.23 1.91,22.86 1.91,28.26 2.54,28.89 2.54,30.8 1.91,31.43 1.91,36.83 2.54,37.47 9.27,37.47 10.54,36.2 12.06,36.2 12.95,37.08 23.11,37.08 23.37,36.83 23.37,27.43 23.11,27.18 21.34,27.18 17.65,23.5
VDD_PLL on BOTTOM: 43.56,33.53 44.07,33.02 44.2,33.02 45.09,33.91 45.09,34.16 44.7,34.54 44.7,35.43 43.97,36.16 43.97,36.45 43.47,36.45 43.47,35.78 43.56,35.69
VDD_PLL on BOTTOM: 38.48,28.07 39.12,28.07 39.24,28.19 40.77,28.19 41.02,27.94 41.02,27.3 40.77,27.05 39.62,27.05 39.12,27.56 38.48,27.56
VDD_PLL on BOTTOM: 48.51,20.07 48.51,22.73 48.77,22.99 48.77,25.15 48.51,25.4 47.75,25.4 47.5,25.15 47.5,21.21 48.01,20.7 48.01,20.07
VDD_PLL on LYR4: 39.75,28.19 40.89,28.19 41.15,27.94 41.15,27.3 40.89,27.05 38.61,27.05 38.35,27.3 38.35,31.62 38.48,31.75 39.37,31.75 39.5,31.62 39.5,28.45
VDD_PLL on LYR5_PWR: 40.64,27.43 40.77,27.3 42.42,27.3 42.67,27.56 46.35,27.56 47.12,26.8 47.12,25.15 47.24,25.02 48.9,25.02 49.15,25.27 49.15,28.7 48.9,28.96 42.67,28.96 42.29,28.57 42.29,28.19 42.04,27.94 40.77,27.94 40.64,27.81
VDDS on BOTTOM: 47.88,35.49 47.56,35.81 47.56,36.45 47.08,36.45 47.08,35.81 46.74,35.47 46.74,33.91 46.35,33.53 46.35,33.15 46.48,33.02 47.24,33.02 47.88,33.66
VDDS on BOTTOM: 38.61,22.61 39.37,22.61 39.62,22.86 39.62,23.62 39.88,23.88 41.27,23.88 41.53,24.13 41.53,24.51 41.66,24.64 41.91,24.64 42.04,24.77 42.04,25.4 41.91,25.53 41.27,25.53 40.51,26.29 39.62,26.29 39.37,26.04 39.37,25.27 39.12,25.02 38.48,25.02 38.48,22.73
VDDS on LYR4: 46.23,25.65 45.97,25.91 45.97,28.83 45.72,29.08 45.72,29.34 45.97,29.59 45.97,34.54 46.23,34.8 49.15,34.8 49.4,34.54 49.4,24.26 49.15,24 48.01,24 47.75,24.26 47.75,25.4 47.5,25.65
VDDS on LYR5_PWR: 42.67,24.89 41.53,24.89 41.4,25.02 41.4,25.4 42.42,26.42 42.42,26.92 42.8,27.3 46.23,27.3 46.86,26.67 46.86,25.78 46.74,25.65 43.05,25.65 42.8,25.4 42.8,25.02
VDDS_DDR on LYR3: 60.33,6.1 60.33,2.86 60.01,2.54 18.67,2.54 18.41,2.79 18.41,8.38 18.67,8.64 27.18,8.64 29.72,6.1 45.85,6.1 46.1,6.35 60.07,6.35
VDDS_DDR on LYR5_PWR: 49.4,30.35 49.4,25.27 49.66,25.02 50.04,25.02 50.29,24.77 50.29,20.7 49.4,19.81 49.4,5.84 49.85,5.4 60.33,5.4 60.64,5.71 60.64,15.88 60.96,16.19 70.17,16.19 70.48,16.51 70.48,33.97 70.17,34.29 50.67,34.29 50.42,34.04 50.42,31.37
HDMI_1V8 on LYR5_PWR: 54.1,34.8 54.36,34.54 70.1,34.54 70.36,34.8 70.36,44.58 70.1,44.83 68.83,44.83 67.94,45.72 60.07,45.72 59.18,44.83 54.36,44.83 54.1,44.58
P_L1 on TOP: 23.18,11.06 23.18,10.74 22.61,10.16 22.23,10.16 22.1,10.03 22.1,9.78 22.35,9.53 23.5,9.53 23.75,9.78 23.75,11.11 23.5,11.37
P_L2 on TOP: 24.64,9.53 24.38,9.78 24.38,10.67 24.51,10.79 24.51,11.46 24.64,11.59 24.73,11.59 25.53,10.79 25.53,9.78 25.27,9.53
P_L3 on TOP: 26.44,15.34 25.91,15.34 25.91,15.56 26.73,15.56 27.3,16.13 27.3,17.53 27.56,17.78 29.34,17.78 29.46,17.65 29.46,17.14 29.34,17.02 28.19,17.02 28.07,16.89 28.07,15.75 27.56,15.24 26.54,15.24
SYS_5V on BOTTOM: 8.72,16.13 10.01,16.13 10.07,16.07 10.07,15.6 9.45,14.97 8.67,14.97 8.51,15.14 8.51,15.91
SYS_5V on BOTTOM: 18.08,15.07 19.06,15.07 19.38,14.76 20.47,14.76 20.59,14.64 20.59,13.79 20.45,13.65 18.16,13.65 17.91,13.91 17.91,14.9
SYS_5V on LYR5_PWR: 83.5,20.64 75.25,20.64 73.98,21.91 73.98,22.86 73.47,23.37 71.18,23.37 70.8,22.99 70.8,16.19 70.48,15.88 61.28,15.88 60.96,15.56 60.96,5.4 60.64,5.08 26.35,5.08 26.04,4.76 26.04,1.59 26.35,1.27 75.88,1.27 77.15,2.54 77.15,8.26 76.52,8.89 74.61,8.89 73.98,9.53 73.98,11.11 74.61,11.75 83.5,11.75 84.14,12.38 84.14,20
USB_DC on TOP: 19.95,13.04 19.19,13.04 18.61,12.46 18.61,11.61 18.77,11.44 19.66,11.44 20.08,11.86 20.08,12.92
VDCDC1 on TOP: 20.07,10.73 22.23,10.73 22.96,11.47 22.96,12.19 23.16,12.19 23.16,11.29 22.99,11.11 22.99,10.79 22.48,10.29 21.84,10.29 21.59,10.03 21.59,9.78 21.34,9.53 20.07,9.53 19.81,9.78 19.81,10.48
VRTC on LYR3: 48.51,24.64 47.75,24.64 47.5,24.38 47.5,21.59 47.12,21.21 47.12,20.83 47.24,20.7 49.28,20.7 49.4,20.83 49.4,21.21 48.77,21.84 48.77,24.38
VRTC on LYR5_PWR: 47.37,20.32 49.53,20.32 50.04,20.83 50.04,24.64 49.91,24.77 47.24,24.77 47.12,24.64 47.12,20.57

Small or netless copper shapes (teardrops, artwork), in the pictures only: 456 on TOP, 313 on BOTTOM, 1 on LYR2_GND, 172 on LYR3, 114 on LYR4, 10 on LYR5_PWR

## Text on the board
BOTTOM: PCB RevC | LAYER 6 | SOLDER
Board Geometry/Soldermask Bottom: SMS
Ref Des/Silkscreen Bottom: S/N | BSLK
TOP: LAYER 1 | COMPONENT
Board Geometry/Soldermask Top: SMC
Ref Des/Silkscreen Top: USER LEDS | 0 | 1 | 2 | 3 | RESET | POWER | PWR | USB | 10/100 Ethernet | AM335x | USB Host | HDMI | microSD Card | TSLK
LYR2_GND: LAYER 2 | GROUND
LYR3: LAYER 3 | SIGNAL
LYR4: LAYER 4 | SIGNAL
LYR5_PWR: LAYER 5 | POWER
DISPLAY_BOTTOM: SPS
DISPLAY_TOP: 1 | SPC
DIMENSION: (OZ) | LAYER 1 - PRIMARY SIDE - SIGNAL | LAYER 2 - GROUND PLANE | LAYER 3 - SIGNAL | LAYER 4 - SIGNAL | LAYER 5 - SPLIT POWER PLANE | LAYER 6 - SECONDARY SIDE - SIGNAL | LAYER# | COPPER WEIGHT | HALF+PLATING | IMPEDANCE CONTROL | +/- 10% | 50ohm SINGLE ENDED | TRACE WIDTH | TRACE WIDTH / SPACE | 90ohm DIFFERENTIAL | 100ohm DIFFERENTIAL | 9. ALL VIAS TO HAVE SOLDERMASK. | FINISHED AS SMOOTH WALL BY VEDOR. | PROCESS NOTES: | 2. APPLY LPI SOLDERMASK OVER BARE COPPER (SMOBC), | COLOR: BLACK. SOLDERMASK SHALL CONFIRM TO IPC-SM-840. | CLASS H. CURRENT REV. | 3. SOLDERMASK ARTWORK HAS ZERO (0) OVERSIZED PADS. | FABRICATION VENDOR IS ALLOWED TO ADJUST THE COMPONENT | SOLDERMASK PADS TO MEET THEIR TOOLING REQUIREMENTS. | 4. APPLY LPI SILKSCREEN OR EQUIVALENT PER THE ARTWORK. | COLOR: WHITE. | 1. PLATE ALL EXPOSED AREAS WITH ELECTROLESS | IMMERSION GOLD, NICKEL 150 MICROINCHES THK MIN | GOLD 5-15 MICROINCHES THK MIN. | SUPPLIED IPC-D-356 NETLIST. | FAB NOTES: | 1. ALL DIMENSIONS ARE IN INCHES, UNLESS | OTHERWISE NOTED. | 2. THE PWB SHALL BE FABRICATED TO IPC-6012, | CLASS 2 AND WORKMANSHIP SHALL CONFORM TO | IPC-A-600, CLASS 2. CURRENT REVISIONS. | 3. BOARD MATERIAL SHALL BE 180 Tg/350 Td ISOLA FR-370HR | OR EQUIVALENT, RoHS COMPLIANT AND LEAD FREE | ASSEMBLY CAPABLE.  BOARD MATERIAL SHALL | MEET OR EXCEED IPC-4101B. COLOR: NATURAL. | 4. BOARD MATERIAL & CONSTRUCTION TO BE U.L. | APPROVED AND MARKED ON THE FINISHED BOARD. | 5. MINIMUM COPPER WALL THICKNESS OF PLATED-THRU | HOLES TO BE .001 INCH, WITH A MINIMUM | ANNULAR RING OF .002 INCH. | 6. OVERALL BOARD THICKNESS TO BE .062 +/- 10% | AND APPLIES AFTER ALL LAMINATION AND PLATING | PROCESSES, MEASURED FROM COPPER TO COPPER. | 7. MAX. WARP & TWIST TO BE .0075 INCHES PER INCH. | 8. BOARD MUST BE ELECTRICALLY TESTED USING | 1 | 5.25 | 4.75 | 4.5/6.5 | 5.0/7.0 | 3.75/7.25 | 4.00/8.00 | R.250 2X | LAYER STACK-UP - ALL DIMENSIONS IN INCHES
USER_PART_NUM_TOP: TSLKC
USER_PART_NUM_BOTTOM: BSLKC
User.14: DATE | DESIGN ENGR | PROJECT ENGR | ENGR MGR | NEXT ASSEMBLY | APPROVED | CHECKED | DRAFTING | ENGR | NONE | 1 OF 1
User.15: C100 | C73 | C97 | C98 | C99 | C25 | C48 | C46 | C58 | C41 | C66 | C65 | C60 | C70 | C26 | C87 | C45 | C79 | C54 | C44 | C82 | C83 | R49 | C84 | C69 | R158 | C71 | C86 | C85 | C67 | C38 | C78 | C52 | C53 | C51 | R116 | R131 | R140 | R134 | R145 | R113 | R138 | R115 | R112 | R114 | R117 | C134 | R150 | R154 | R155 | R153 | C154 | R151 | R152 | C68 | C43 | C50 | C81 | C56 | C42 | C47 | R17 | C49 | C72 | C88 | C106 | C94 | C63 | C80 | FB1 | C40 | C39 | D2 | D3 | D4 | D5 | USER LEDS | 0 | 1 | 2 | 3 | D1 | RESET | C19 | R10 | R72 | R73 | R74 | R71 | POWER | R9 | R7 | U10 | C1 | TP5 | TP6 | C16 | C3 | R5 | TP7 | TP8 | TP9 | C9 | C12 | P | R119 | R118 | A | R139 | R133 | R128 | R127 | R126 | R125 | R124 | R28 | 14 | 18 | U3 | Y4 | R27 | TP3 | V | TP1 | C96 | 16 | TP2 | 64 | 17 | 32 | 49 | 33 | R157 | R95 | C61 | R166 | D8 | 46 | 45 | U9 | 19 | R147 | R146 | C117 | C119 | R96 | R99 | C120 | C121 | C116 | C118 | FB7 | C151 | C114 | C115 | C122 | FB8 | R98 | C123 | R100 | C124 | R97 | C109 | C110 | C112 | C113 | C107 | C108 | C111 | R22 | C28 | U15 | FB2 | U6 | FB3 | C64 | C77 | R14 | C24 | C30 | L3 | U7 | C135 | C136 | R103 | C14 | C8 | L2 | R108 | R156 | R159 | C126 | C133 | C132 | C131 | C13 | FB4 | C7 | L1 | R144 | R129 | R123 | R122 | R121 | R120 | U4 | C137 | C140 | C138 | C139 | C141 | R137 | R11 | C17 | 5 | R135 | C2 | R12 | R132 | R130 | C | E | G | J | L | N | R | 7 | 9 | PWR | TP4 | R8 | Q2 | Q1 | C18 | R3 | R4 | C11 | C37 | C55 | U16 | C29 | R50 | R24 | R23 | R25 | C32 | C165 | C31 | C57 | R29 | C33 | C27 | R81 | R80 | R84 | C93 | R45 | R48 | R82 | R46 | R47 | R165 | R83 | C168 | C166 | R85 | C167 | C157 | R86 | R87 | R88 | R89 | R90 | R91 | C169 | C156 | C160 | C163 | R92 | R93 | R94 | R75 | C173 | C153 | R52 | C35 | C171 | R53 | C76 | C149 | R148 | R149 | C150 | C148 | C147 | C146 | R70 | R69 | R68 | R67 | C145 | C144 | R66 | R65 | R64 | R63 | C172 | C155 | FB5 | C75 | R62 | C95 | C103 | R61 | R101 | R60 | C170 | C102 | R105 | R58 | C162 | R30 | R102 | C101 | R57 | C161 | C22 | R110 | R54 | R59 | R106 | C74 | C21 | R26 | R109 | R55 | C164 | C104 | R164 | R21 | R56 | C92 | R163 | C105 | C89 | C91 | C90 | C59 | R20 | R19 | R167 | R18 | C158 | R51 | C159 | 20 | R160 | C62 | R161 | C125 | C130 | C129 | R162 | R111 | R104 | C128 | C152 | C127 | R107 | C143 | C15 | R142 | R1 | R141 | R143 | R6 | C4 | C10 | C142 | R77 | C36 | R76 | R79 | R78 | C20 | R136 | DATE | DESIGN ENGR | PROJECT ENGR | ENGR MGR | NEXT ASSEMBLY | APPROVED | CHECKED | DRAFTING | ENGR | 1 OF 1 | USB | S1 | P1 | P5 | U13 | U2 | U14 | Y3 | U5 | J1 | Y1 | AM335x | C34 | U11 | U12 | RT1 | D7 | D6 | S2 | P3 | P8 | P9 | USB Host | HDMI | P6 | P10 | U8 | S/N | Y2 | P4 | S3 | 10/100 Ethernet | microSD Card | P2 | ASSEMBLY SOLDER SIDE
User.16: NONE
User.29: FIGURE | FINISHED_SIZE | 6.0 | 8.0 | 12.0 | 35.0 | 40.0 | 63.0 | 125.0 | 128.0 | ROTATION | - | DRILL CHART: TOP to BOTTOM | ALL UNITS ARE IN MILS | TOLERANCE_DRILL | +3.0/-3.0 | +5.0/-5.0 | TOLERANCE_TRAVEL | PLATED | NON-PLATED | QTY | 29 | 801 | 30 | 97 | 26 | 2 | 4 | 991 | TOTAL HOLES:
User.31: FIGURE | FINISHED_SIZE | 50.0x15.0 | 95.0x40.0 | 120.0x40.0 | 140.0x40.0 | ROTATION | 0.000 | 90.000 | SLOT HOLES: TOP to BOTTOM | ALL UNITS ARE IN MILS | TOLERANCE_DRILL | +3.0/-3.0 | TOLERANCE_TRAVEL | PLATED | QTY | 2 | 1 | 7 | TOTAL HOLES:
